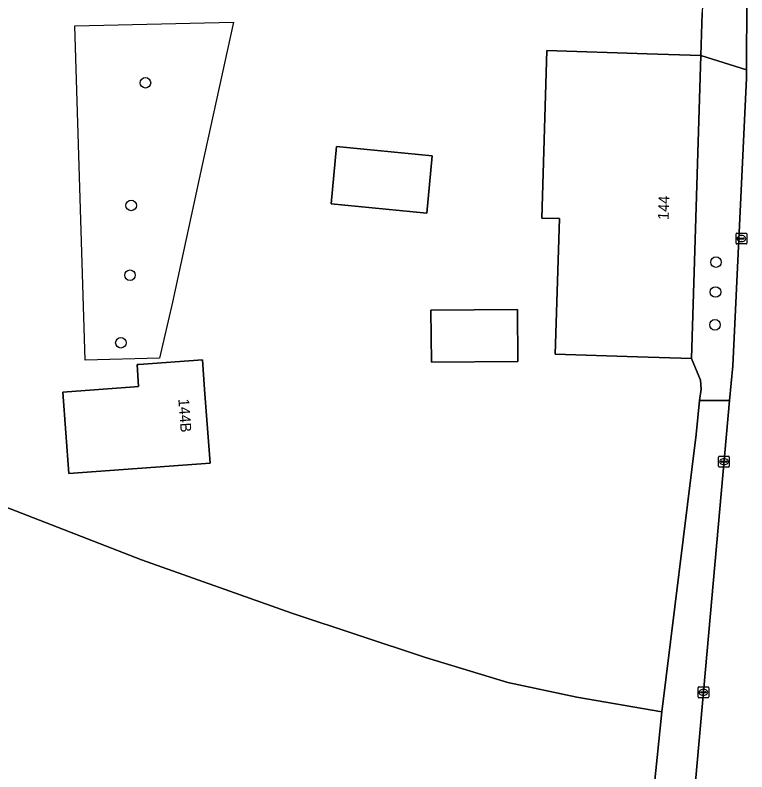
# Model space of a CAD drawing. Extents: x 160203 to 161530, y 379528 to 381797.
# Drawn here: x 160748 to 160815.8, y 380629 to 380699.1 of the extents above; entities that cross this region are included whole.
import ezdxf

# ---------------------------------------------------------------- set-up
doc = ezdxf.new("R2010")
doc.units = 0
for name, color, linetype in [('IMGEO_Boom', 7, 'Continuous'), ('IMGEO_Erf', 7, 'Continuous'), ('IMGEO_Grasland_agrarisch', 7, 'Continuous'), ('IMGEO_Groenvoorziening', 7, 'Continuous'), ('IMGEO_Hek', 7, 'Continuous'), ('IMGEO_Kolk', 7, 'Continuous'), ('IMGEO_Pand', 7, 'Continuous'), ('IMGEO_Pand_nummerreeks', 7, 'Continuous'), ('IMGEO_Rijbaan_lokaal_gesloten', 7, 'Continuous'), ('IMGEO_Voetpad_open', 7, 'Continuous')]:
    doc.layers.add(name, color=color, linetype=linetype)

msp = doc.modelspace()

# ---------------------------------------------------------------- linework, layer by layer
at = {"layer": 'IMGEO_Boom'}
for centre in [(160760.04, 380692.81), (160758.717, 380681.441), (160812.909, 380676.192), (160758.611, 380674.975), (160812.86, 380673.424), (160812.811, 380670.377), (160757.764, 380668.721)]:
    msp.add_circle(centre, 0.489, dxfattribs=at)
at = {"layer": 'IMGEO_Erf'}
msp.add_lwpolyline([(160653.078, 380673.311), (160667.676, 380659.508), (160672.964, 380654.698), (160732.123, 380658.891), (160735.875, 380657.838), (160759.659, 380648.601), (160773.611, 380643.676), (160785.98, 380639.572), (160793.624, 380637.245), (160800.015, 380635.877), (160807.89, 380634.509), (160811.078, 380660.23), (160811.37, 380663.358), (160811.539, 380664.407), (160811.456, 380665.257), (160810.635, 380667.262), (160805.638, 380667.419), (160798.017, 380667.659), (160798.411, 380680.225), (160796.755, 380680.277), (160797.243, 380695.785), (160806.52, 380695.494), (160811.517, 380695.337), (160811.631, 380699.294)], dxfattribs=at)
for points in [[(160777.757, 380686.887), (160786.605, 380686.042), (160786.098, 380680.74), (160777.25, 380681.586)], [(160786.498, 380671.726), (160794.511, 380671.809), (160794.559, 380666.985), (160786.534, 380666.927)], [(160759.016, 380664.631), (160759.41, 380664.66), (160759.261, 380666.691), (160759.435, 380666.704), (160765.321, 380667.14), (160765.524, 380664.387), (160766.028, 380657.566), (160752.934, 380656.597), (160752.376, 380664.14)]]:
    msp.add_lwpolyline(points, close=True, dxfattribs=at)
at = {"layer": 'IMGEO_Grasland_agrarisch'}
msp.add_lwpolyline([(160806.333, 380619.409), (160807.89, 380634.509), (160800.015, 380635.877), (160793.624, 380637.245), (160785.98, 380639.572), (160773.611, 380643.676), (160759.659, 380648.601), (160735.875, 380657.838), (160724.413, 380609.361), (160726.913, 380607.468), (160734.981, 380601.724), (160743.595, 380596.079), (160750.384, 380591.884), (160752.717, 380590.443), (160764.753, 380583.637), (160772.849, 380578.66), (160776.314, 380576.149), (160790.192, 380567.674), (160793.641, 380565.361), (160801.244, 380562.921), (160802.874, 380583.321), (160803.41, 380589.083), (160804.861, 380605.066)], close=True, dxfattribs=at)
at = {"layer": 'IMGEO_Groenvoorziening'}
msp.add_lwpolyline([(160809.998, 380616.634), (160814.161, 380663.374), (160811.37, 380663.358), (160811.078, 380660.23), (160807.89, 380634.509), (160806.333, 380619.409), (160804.861, 380605.066), (160803.41, 380589.083), (160802.874, 380583.321), (160801.244, 380562.921), (160804.651, 380561.649), (160805.988, 380576.064), (160806.416, 380576.035), (160807.06, 380582.557)], close=True, dxfattribs=at)
at = {"layer": 'IMGEO_Hek'}
for points in [[(160762.542, 380672.477), (160761.33, 380667.292), (160754.447, 380667.1), (160753.51, 380698.094), (160768.191, 380698.421), (160765.279, 380685.047), (160762.542, 380672.477)], [(160802.874, 380583.321), (160803.41, 380589.083), (160804.861, 380605.066), (160806.333, 380619.409), (160807.89, 380634.509)]]:
    msp.add_lwpolyline(points, dxfattribs=at)
at = {"layer": 'IMGEO_Kolk'}
for p, q in [((160814.766, 380677.948), (160814.766, 380678.8)), ((160814.841, 380678.874), (160815.693, 380678.874)), ((160815.254, 380678.654), (160815.279, 380678.654)), ((160815.767, 380678.8), (160815.767, 380677.948)), ((160815.025, 380678.368), (160815.025, 380678.38)), ((160815.463, 380678.331), (160815.065, 380678.331)), ((160815.068, 380678.417), (160815.466, 380678.417)), ((160815.277, 380678.094), (160815.252, 380678.094)), ((160815.509, 380678.38), (160815.509, 380678.368)), ((160815.693, 380677.874), (160814.841, 380677.874)), ((160813.141, 380657.275), (160813.141, 380658.127)), ((160813.216, 380658.201), (160814.068, 380658.201)), ((160813.4, 380657.695), (160813.4, 380657.707)), ((160813.838, 380657.658), (160813.44, 380657.658)), ((160813.443, 380657.744), (160813.841, 380657.744)), ((160813.629, 380657.981), (160813.654, 380657.981)), ((160813.884, 380657.707), (160813.884, 380657.695)), ((160814.142, 380658.127), (160814.142, 380657.275)), ((160814.068, 380657.201), (160813.216, 380657.201)), ((160813.652, 380657.421), (160813.627, 380657.421)), ((160811.242, 380635.908), (160811.242, 380636.76)), ((160811.317, 380636.834), (160812.169, 380636.834)), ((160811.73, 380636.614), (160811.755, 380636.614)), ((160812.243, 380636.76), (160812.243, 380635.908)), ((160811.501, 380636.328), (160811.501, 380636.34)), ((160811.939, 380636.291), (160811.541, 380636.291)), ((160811.544, 380636.377), (160811.942, 380636.377)), ((160811.753, 380636.054), (160811.728, 380636.054)), ((160811.985, 380636.34), (160811.985, 380636.328)), ((160812.169, 380635.834), (160811.317, 380635.834))]:
    msp.add_line(p, q, dxfattribs=at)
for points in [[(160814.766, 380677.948), (160814.766, 380678.8)], [(160814.841, 380678.874), (160815.693, 380678.874)], [(160815.767, 380678.8), (160815.767, 380677.948)], [(160815.693, 380677.874), (160814.841, 380677.874)], [(160813.141, 380657.275), (160813.141, 380658.127)], [(160813.216, 380658.201), (160814.068, 380658.201)], [(160814.142, 380658.127), (160814.142, 380657.275)], [(160814.068, 380657.201), (160813.216, 380657.201)], [(160811.242, 380635.908), (160811.242, 380636.76)], [(160811.317, 380636.834), (160812.169, 380636.834)], [(160812.243, 380636.76), (160812.243, 380635.908)], [(160812.169, 380635.834), (160811.317, 380635.834)]]:
    msp.add_lwpolyline(points, dxfattribs=at)
for centre, radius, start, end in [((160814.843, 380678.798), 0.0765, 91.55205, 178.44795), ((160814.843, 380678.798), 0.0765, 91.55205, 178.44795), ((160815.691, 380678.798), 0.0765, 1.55205, 88.44795), ((160815.691, 380678.798), 0.0765, 1.55205, 88.44795), ((160814.843, 380677.95), 0.0765, 181.55205, 268.44795), ((160814.843, 380677.95), 0.0765, 181.55205, 268.44795), ((160815.065, 380678.377), 0.0403, 85.87752, 175.75265), ((160815.062, 380678.367), 0.0366, 178.93798, 274.71019), ((160815.466, 380678.374), 0.043, 264.86636, 352.45326), ((160815.47, 380678.379), 0.0386, 1.73085, 96.63898), ((160815.691, 380677.95), 0.0765, 271.55205, 358.44795), ((160815.691, 380677.95), 0.0765, 271.55205, 358.44795), ((160813.218, 380658.125), 0.0765, 91.55205, 178.44795), ((160813.218, 380658.125), 0.0765, 91.55205, 178.44795), ((160813.44, 380657.704), 0.0403, 85.87752, 175.75265), ((160813.437, 380657.694), 0.0366, 178.93798, 274.71019), ((160813.841, 380657.701), 0.043, 264.86636, 352.45326), ((160813.845, 380657.706), 0.0386, 1.73085, 96.63898), ((160814.066, 380658.125), 0.0765, 1.55205, 88.44795), ((160814.066, 380658.125), 0.0765, 1.55205, 88.44795), ((160813.218, 380657.277), 0.0765, 181.55205, 268.44795), ((160813.218, 380657.277), 0.0765, 181.55205, 268.44795), ((160814.066, 380657.277), 0.0765, 271.55205, 358.44795), ((160814.066, 380657.277), 0.0765, 271.55205, 358.44795), ((160811.319, 380636.758), 0.0765, 91.55205, 178.44795), ((160811.319, 380636.758), 0.0765, 91.55205, 178.44795), ((160812.167, 380636.758), 0.0765, 1.55205, 88.44795), ((160812.167, 380636.758), 0.0765, 1.55205, 88.44795), ((160811.319, 380635.91), 0.0765, 181.55205, 268.44795), ((160811.319, 380635.91), 0.0765, 181.55205, 268.44795), ((160811.541, 380636.337), 0.0403, 85.87752, 175.75265), ((160811.538, 380636.327), 0.0366, 178.93798, 274.71019), ((160811.942, 380636.334), 0.043, 264.86636, 352.45326), ((160811.946, 380636.339), 0.0386, 1.73085, 96.63898), ((160812.167, 380635.91), 0.0765, 271.55205, 358.44795), ((160812.167, 380635.91), 0.0765, 271.55205, 358.44795)]:
    msp.add_arc(centre, radius, start, end, dxfattribs=at)
for centre, major_axis, ratio, start_param, end_param in [((160815.253, 380678.374), (-0.387, 0.002), 0.722429, 4.712389, 7.853982), ((160815.278, 380678.374), (-0.39, 0.002), 0.717154, 1.570796, 4.712389), ((160813.628, 380657.701), (-0.387, 0.002), 0.722429, 4.712389, 7.853982), ((160813.653, 380657.701), (-0.39, 0.002), 0.717154, 1.570796, 4.712389), ((160811.729, 380636.334), (-0.387, 0.002), 0.722429, 4.712389, 7.853982), ((160811.754, 380636.334), (-0.39, 0.002), 0.717154, 1.570796, 4.712389)]:
    msp.add_ellipse(centre, major_axis=major_axis, ratio=ratio, start_param=start_param, end_param=end_param, dxfattribs=at)
at = {"layer": 'IMGEO_Pand'}
for points in [[(160811.517, 380695.337), (160806.52, 380695.494), (160797.243, 380695.785), (160796.755, 380680.277), (160798.411, 380680.225), (160798.017, 380667.659), (160805.638, 380667.419), (160810.635, 380667.262)], [(160777.25, 380681.586), (160786.098, 380680.74), (160786.605, 380686.042), (160777.757, 380686.887)], [(160786.534, 380666.927), (160794.559, 380666.985), (160794.511, 380671.809), (160786.498, 380671.726)], [(160765.524, 380664.387), (160765.321, 380667.14), (160759.435, 380666.704), (160759.261, 380666.691), (160759.41, 380664.66), (160759.016, 380664.631), (160752.376, 380664.14), (160752.934, 380656.597), (160766.028, 380657.566)]]:
    msp.add_lwpolyline(points, close=True, dxfattribs=at)
at = {"layer": 'IMGEO_Rijbaan_lokaal_gesloten'}
msp.add_lwpolyline([(160815.749, 380700.692), (160815.747, 380694.014), (160815.747, 380693.241), (160814.474, 380666.576), (160814.161, 380663.374), (160809.998, 380616.634), (160807.06, 380582.557), (160806.416, 380576.035), (160803.96, 380549.663)], dxfattribs=at)
at = {"layer": 'IMGEO_Voetpad_open'}
for points in [[(160815.749, 380700.692), (160815.733, 380701.445), (160813.031, 380701.385), (160811.709, 380701.354), (160811.631, 380699.294), (160811.517, 380695.337), (160815.747, 380694.014)], [(160815.747, 380693.241), (160815.747, 380694.014), (160811.517, 380695.337), (160810.635, 380667.262), (160811.456, 380665.257), (160811.539, 380664.407), (160811.37, 380663.358), (160814.161, 380663.374), (160814.474, 380666.576)]]:
    msp.add_lwpolyline(points, close=True, dxfattribs=at)

# ---------------------------------------------------------------- texts
at = {"layer": 'IMGEO_Pand_nummerreeks'}
for s, rotation, p in [('144', 88.2006, (160808.517, 380680.093)), ('144B', 274.22822, (160763.082, 380663.5))]:
    msp.add_text(s, height=1, rotation=rotation, dxfattribs=at).set_placement(p)

doc.saveas('drawing.dxf')
